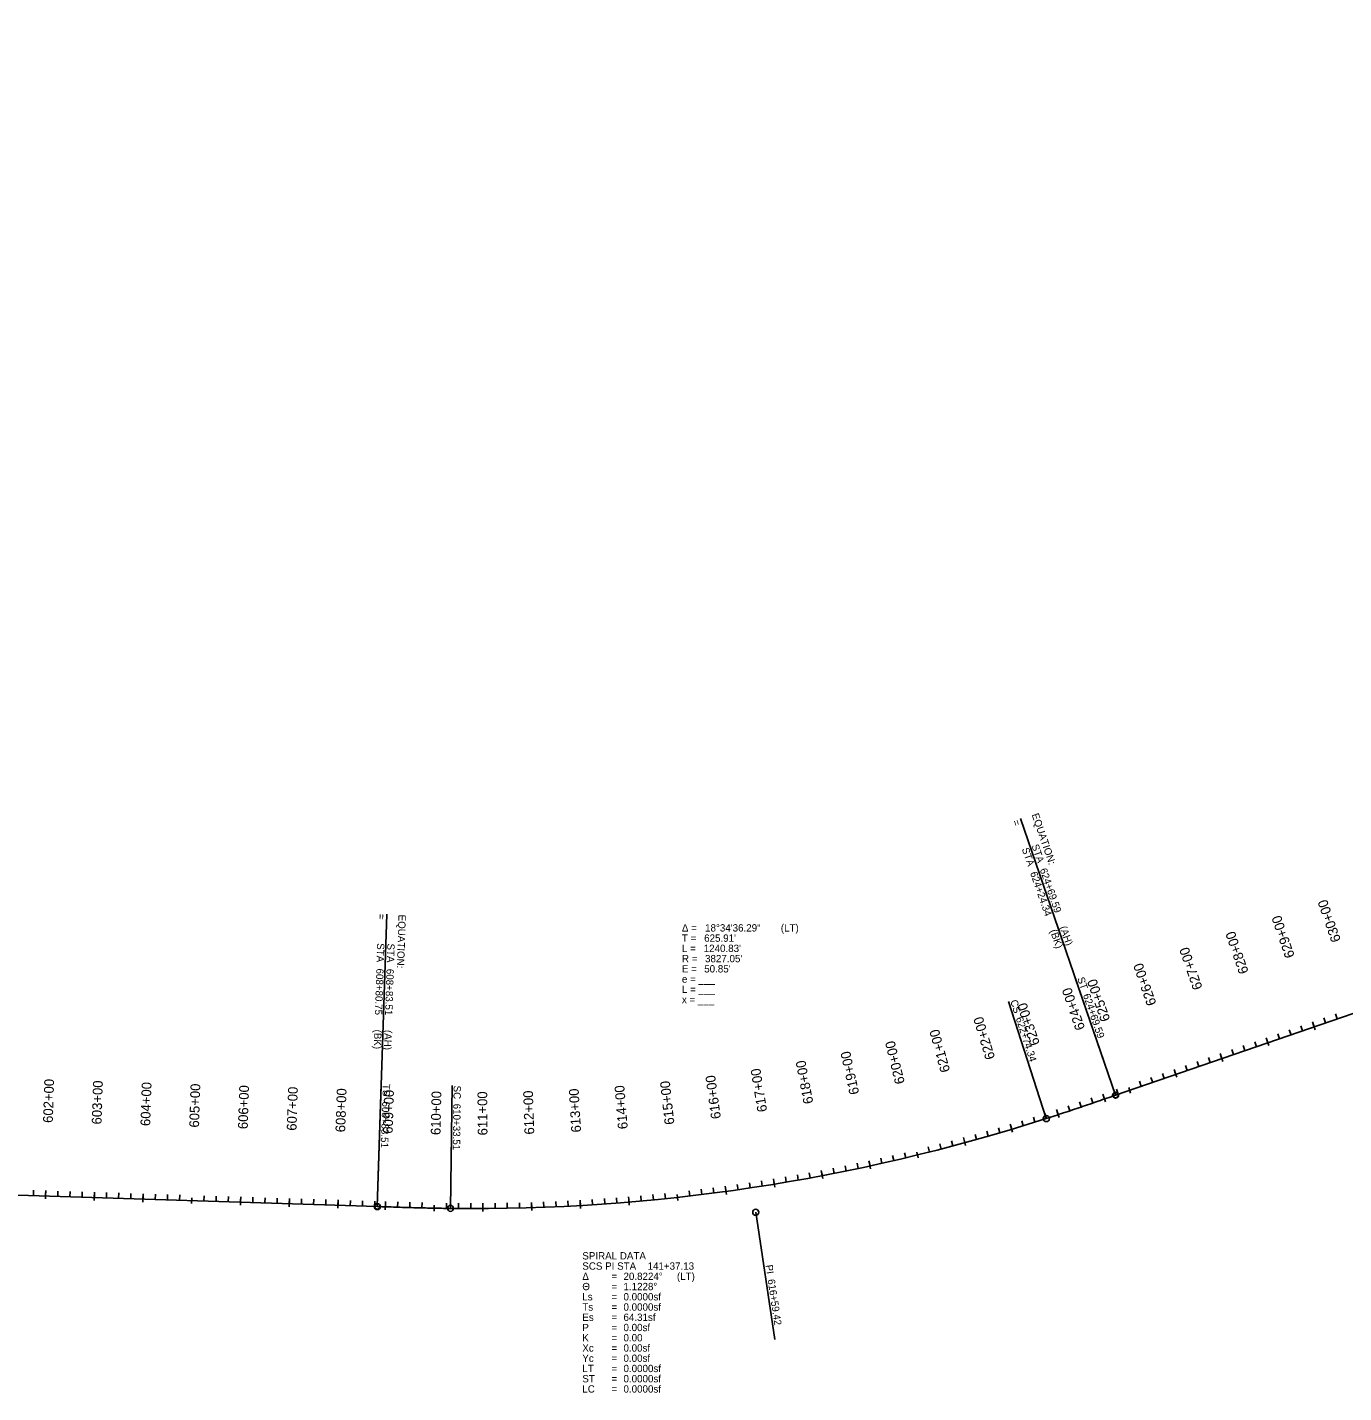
# Model space of a CAD drawing. Extents: x 22693007 to 22771804, y 6223023 to 6251673.
# Drawn here: x 22737783 to 22740482, y 6235125 to 6237925 of the extents above; entities that cross this region are included whole.
import ezdxf

# ---------------------------------------------------------------- set-up
doc = ezdxf.new("R2010")
doc.units = 0
for name, color, linetype in [('Default', 7, 'Continuous'), ('Draft_2', 7, 'Continuous'), ('NamedBoundary', 7, 'Continuous'), ('SheetBorder', 7, 'Continuous'), ('TextAlignment', 7, 'Continuous')]:
    doc.layers.add(name, color=color, linetype=linetype)

msp = doc.modelspace()

# ---------------------------------------------------------------- linework, layer by layer
at = {"layer": 'Default'}
for p, q in [((22740013.9, 6235734.9), (22746376.2, 6237924.7)), ((22734977.1, 6235619), (22738500.2, 6235506.5))]:
    msp.add_line(p, q, dxfattribs=at)
msp.add_arc((22738697.4, 6239329.4), 3827, 269.2933, 287.8701, dxfattribs=at)
for points in [[(22739871.8, 6235687), (22739883.7, 6235690.8), (22739907.4, 6235698.6), (22739943, 6235710.6), (22739978.5, 6235722.7), (22740002.1, 6235730.8), (22740013.9, 6235734.9)], [(22738500.2, 6235506.5), (22738512.7, 6235506.1), (22738537.7, 6235505.3), (22738575.2, 6235504.2), (22738612.7, 6235503.2), (22738637.7, 6235502.8), (22738650.2, 6235502.7)]]:
    msp.add_open_spline(points, degree=3, dxfattribs=at)
at = {"layer": 'Draft_2'}
for p, q in [((22740420.9, 6235875), (22740417.3, 6235885.3)), ((22740326.3, 6235842.4), (22740322.8, 6235852.8)), ((22740231.8, 6235809.9), (22740228.2, 6235820.2)), ((22740137.2, 6235777.3), (22740133.7, 6235787.7)), ((22739990.9, 6235727), (22739987.4, 6235737.3)), ((22740040.7, 6235750.6), (22740044.7, 6235739)), ((22739896.2, 6235695), (22739892.8, 6235705.3)), ((22739800.8, 6235664.9), (22739797.7, 6235675.3)), ((22739704.7, 6235637.3), (22739701.8, 6235647.8)), ((22739606.4, 6235618.2), (22739609.3, 6235606.3)), ((22739510.4, 6235589.7), (22739508.1, 6235600.4)), ((22739314, 6235552.4), (22739312.2, 6235563.1)), ((22739412.5, 6235569.8), (22739410.4, 6235580.5)), ((22737819.8, 6235528.2), (22737820.2, 6235539.1)), ((22737919.8, 6235525), (22737920.1, 6235535.9)), ((22738019.7, 6235521.8), (22738020.1, 6235532.7)), ((22739215.1, 6235537.5), (22739213.6, 6235548.4)), ((22738119.9, 6235524.7), (22738119.5, 6235512.5)), ((22738219.6, 6235515.4), (22738220, 6235526.3)), ((22738319.6, 6235512.2), (22738319.9, 6235523.2)), ((22738419.5, 6235509), (22738419.9, 6235520)), ((22738516.7, 6235505.9), (22738517.1, 6235516.9)), ((22738616.8, 6235509.3), (22738616.6, 6235497.1)), ((22738716.7, 6235502.4), (22738716.6, 6235513.3)), ((22738816.7, 6235504.2), (22738816.3, 6235515.1)), ((22738916.6, 6235508.6), (22738915.9, 6235519.6)), ((22739016.3, 6235515.7), (22739015.4, 6235526.6)), ((22739115.2, 6235531.4), (22739116.5, 6235519.2))]:
    msp.add_line(p, q, dxfattribs=at)
at = {"layer": 'NamedBoundary'}
for p, q in [((22740013.9, 6235734.9), (22746376.2, 6237924.7)), ((22734977.1, 6235619), (22738500.2, 6235506.5))]:
    msp.add_line(p, q, dxfattribs=at)
msp.add_arc((22738697.4, 6239329.4), 3827, 269.2933, 287.8701, dxfattribs=at)
for points in [[(22739871.8, 6235687), (22739883.7, 6235690.8), (22739907.4, 6235698.6), (22739943, 6235710.6), (22739978.5, 6235722.7), (22740002.1, 6235730.8), (22740013.9, 6235734.9)], [(22738500.2, 6235506.5), (22738512.7, 6235506.1), (22738537.7, 6235505.3), (22738575.2, 6235504.2), (22738612.7, 6235503.2), (22738637.7, 6235502.8), (22738650.2, 6235502.7)]]:
    msp.add_open_spline(points, degree=3, dxfattribs=at)
at = {"layer": 'SheetBorder'}
for p, q in [((22740468.2, 6235891.2), (22740464.6, 6235901.6)), ((22740373.6, 6235858.7), (22740370.1, 6235869)), ((22740397.3, 6235866.8), (22740393.7, 6235877.2)), ((22740418.9, 6235880.8), (22740422.9, 6235869.2)), ((22740444.5, 6235883.1), (22740441, 6235893.4)), ((22740302.7, 6235834.3), (22740299.1, 6235844.6)), ((22740324.3, 6235848.2), (22740328.3, 6235836.6)), ((22740350, 6235850.6), (22740346.4, 6235860.9)), ((22740229.8, 6235815.7), (22740233.8, 6235804.1)), ((22740255.4, 6235818), (22740251.9, 6235828.3)), ((22740279.1, 6235826.2), (22740275.5, 6235836.5)), ((22740160.9, 6235785.5), (22740157.3, 6235795.8)), ((22740184.5, 6235793.6), (22740180.9, 6235803.9)), ((22740208.1, 6235801.7), (22740204.6, 6235812.1)), ((22740066.3, 6235752.9), (22740062.8, 6235763.3)), ((22740089.9, 6235761.1), (22740086.4, 6235771.4)), ((22740113.6, 6235769.2), (22740110, 6235779.5)), ((22740135.2, 6235783.1), (22740139.2, 6235771.5)), ((22739967.3, 6235718.9), (22739963.7, 6235729.2)), ((22739988.9, 6235732.8), (22739992.9, 6235721.2)), ((22740019, 6235736.7), (22740015.5, 6235747)), ((22740040.7, 6235750.6), (22740044.7, 6235739)), ((22739894.3, 6235700.8), (22739898.1, 6235689.1)), ((22739919.9, 6235702.8), (22739916.4, 6235713.2)), ((22739943.6, 6235710.8), (22739940.1, 6235721.2)), ((22739824.7, 6235672.2), (22739821.5, 6235682.6)), ((22739848.6, 6235679.6), (22739845.3, 6235690)), ((22739872.4, 6235687.2), (22739869, 6235697.6)), ((22739728.8, 6235644), (22739725.8, 6235654.5)), ((22739752.8, 6235650.8), (22739749.8, 6235661.3)), ((22739776.8, 6235657.8), (22739773.8, 6235668.2)), ((22739799, 6235670.7), (22739802.6, 6235659)), ((22739583.6, 6235606.4), (22739581, 6235617)), ((22739606.4, 6235618.2), (22739609.3, 6235606.3)), ((22739632.1, 6235618.3), (22739629.5, 6235628.9)), ((22739656.4, 6235624.5), (22739653.6, 6235635)), ((22739680.5, 6235630.8), (22739677.7, 6235641.4)), ((22739703.1, 6235643.2), (22739706.3, 6235631.4)), ((22739461.5, 6235579.4), (22739459.3, 6235590.1)), ((22739486, 6235584.5), (22739483.7, 6235595.2)), ((22739509.1, 6235595.7), (22739511.7, 6235583.7)), ((22739534.9, 6235595.1), (22739532.5, 6235605.8)), ((22739559.2, 6235600.7), (22739556.8, 6235611.3)), ((22739338.6, 6235556.5), (22739336.8, 6235567.2)), ((22739363.3, 6235560.7), (22739361.4, 6235571.5)), ((22739387.9, 6235565.2), (22739385.9, 6235575.9)), ((22739411.3, 6235575.8), (22739413.6, 6235563.8)), ((22739437, 6235574.5), (22739434.9, 6235585.2)), ((22737794.9, 6235529), (22737795.2, 6235539.9)), ((22737820, 6235534.3), (22737819.7, 6235522.1)), ((22737844.8, 6235527.4), (22737845.2, 6235538.3)), ((22737869.8, 6235526.6), (22737870.2, 6235537.5)), ((22737894.8, 6235525.8), (22737895.2, 6235536.7)), ((22737944.8, 6235524.2), (22737945.1, 6235535.1)), ((22737969.8, 6235523.4), (22737970.1, 6235534.3)), ((22737994.8, 6235522.6), (22737995.1, 6235533.5)), ((22739091, 6235522.7), (22739089.9, 6235533.5)), ((22739140.7, 6235528.1), (22739139.4, 6235539)), ((22739165.5, 6235531.1), (22739164.2, 6235541.9)), ((22739190.3, 6235534.2), (22739188.9, 6235545.1)), ((22739214.3, 6235543.6), (22739215.9, 6235531.5)), ((22739239.9, 6235541), (22739238.3, 6235551.8)), ((22739264.6, 6235544.6), (22739263, 6235555.4)), ((22739289.3, 6235548.4), (22739287.6, 6235559.2)), ((22739313, 6235558.4), (22739315, 6235546.3)), ((22737920, 6235531.1), (22737919.6, 6235518.9)), ((22738019.9, 6235527.9), (22738019.5, 6235515.7)), ((22738044.7, 6235521), (22738045.1, 6235531.9)), ((22738069.7, 6235520.2), (22738070.1, 6235531.1)), ((22738094.7, 6235519.4), (22738095.1, 6235530.3)), ((22738119.9, 6235524.7), (22738119.5, 6235512.5)), ((22738144.7, 6235517.8), (22738145, 6235528.7)), ((22738169.7, 6235517), (22738170, 6235527.9)), ((22738194.7, 6235516.2), (22738195, 6235527.1)), ((22738219.8, 6235521.5), (22738219.4, 6235509.3)), ((22738244.6, 6235514.6), (22738245, 6235525.5)), ((22738269.6, 6235513.8), (22738270, 6235524.7)), ((22738294.6, 6235513), (22738295, 6235524)), ((22738319.8, 6235518.4), (22738319.4, 6235506.1)), ((22738344.6, 6235511.4), (22738344.9, 6235522.4)), ((22738369.6, 6235510.6), (22738369.9, 6235521.6)), ((22738394.6, 6235509.8), (22738394.9, 6235520.8)), ((22738419.7, 6235515.2), (22738419.3, 6235502.9)), ((22738444.5, 6235508.2), (22738444.9, 6235519.2)), ((22738469.5, 6235507.4), (22738469.9, 6235518.4)), ((22738494.5, 6235506.7), (22738494.9, 6235517.6)), ((22738516.9, 6235512.1), (22738516.5, 6235499.8)), ((22738541.7, 6235505.2), (22738542.1, 6235516.1)), ((22738566.7, 6235504.4), (22738567, 6235515.3)), ((22738591.7, 6235503.8), (22738592, 6235514.7)), ((22738616.8, 6235509.3), (22738616.6, 6235497.1)), ((22738641.7, 6235502.8), (22738641.8, 6235513.7)), ((22738666.7, 6235502.5), (22738666.8, 6235513.4)), ((22738691.7, 6235502.4), (22738691.7, 6235513.3)), ((22738716.7, 6235508.5), (22738716.7, 6235496.3)), ((22738741.7, 6235502.6), (22738741.6, 6235513.5)), ((22738766.7, 6235503), (22738766.5, 6235513.9)), ((22738791.7, 6235503.5), (22738791.4, 6235514.4)), ((22738816.5, 6235510.3), (22738816.9, 6235498.1)), ((22738841.7, 6235505.1), (22738841.2, 6235516)), ((22738866.6, 6235506.1), (22738866.1, 6235517)), ((22738891.6, 6235507.3), (22738891, 6235518.2)), ((22738916.2, 6235514.8), (22738916.9, 6235502.5)), ((22738941.5, 6235510.2), (22738940.8, 6235521.1)), ((22738966.5, 6235511.8), (22738965.7, 6235522.7)), ((22738991.4, 6235513.7), (22738990.6, 6235524.6)), ((22739015.8, 6235521.8), (22739016.8, 6235509.6)), ((22739041.2, 6235517.8), (22739040.2, 6235528.7)), ((22739066.1, 6235520.2), (22739065.1, 6235531)), ((22739115.2, 6235531.4), (22739116.5, 6235519.2))]:
    msp.add_line(p, q, dxfattribs=at)
at = {"layer": 'TextAlignment'}
for p, q in [((22740013.9, 6235734.9), (22739818.6, 6236302.2)), ((22739818.6, 6236302.2), (22739818.6, 6236302.2)), ((22738500.2, 6235506.5), (22738519.4, 6236106.2)), ((22738519.4, 6236106.2), (22738519.4, 6236106.2)), ((22740013.9, 6235734.9), (22739931.9, 6235973.2)), ((22739931.9, 6235973.2), (22739931.9, 6235973.2)), ((22739871.8, 6235687), (22739794.4, 6235926.8)), ((22739794.4, 6235926.8), (22739794.4, 6235926.8)), ((22739871.8, 6235687), (22739794.4, 6235926.8)), ((22739794.4, 6235926.8), (22739794.4, 6235926.8)), ((22738500.2, 6235506.5), (22738508.3, 6235758.3)), ((22738508.3, 6235758.3), (22738508.3, 6235758.3)), ((22738650.2, 6235502.7), (22738653.3, 6235754.6)), ((22738650.2, 6235502.7), (22738653.3, 6235754.6)), ((22738653.3, 6235754.6), (22738653.3, 6235754.6)), ((22738653.3, 6235754.6), (22738653.3, 6235754.6)), ((22739276.1, 6235494.9), (22739315.5, 6235233.9)), ((22739315.5, 6235233.9), (22739315.5, 6235233.9))]:
    msp.add_line(p, q, dxfattribs=at)
for centre, radius in [((22740013.9, 6235734.9), 6.24), ((22740013.9, 6235734.9), 5.34), ((22739871.8, 6235687), 6.24), ((22739871.8, 6235687), 6.24), ((22738500.2, 6235506.5), 6.24), ((22738500.2, 6235506.5), 5.34), ((22738650.2, 6235502.7), 6.24), ((22738650.2, 6235502.7), 6.24), ((22739276.1, 6235494.9), 6.24)]:
    msp.add_circle(centre, radius, dxfattribs=at)

# ---------------------------------------------------------------- texts
at = {"layer": 'Draft_2'}
for s, rotation, p in [('630+00', 108.9929, (22740476.1, 6236052.6)), ('625+00', 108.9929, (22740003.3, 6235889.9)), ('620+00', 103.7629, (22739581.9, 6235760.3)), ('605+00', 88.1705, (22738134.5, 6235668.2)), ('615+00', 96.2773, (22739109.4, 6235675.5)), ('610+00', 88.8477, (22738629.7, 6235653))]:
    msp.add_text(s, height=20.04, rotation=rotation, dxfattribs=at).set_placement(p)
at = {"layer": 'SheetBorder'}
for s, rotation, p in [('630+00', 108.9929, (22740476.1, 6236052.6)), ('629+00', 108.9929, (22740381.5, 6236020.1)), ('628+00', 108.9929, (22740287, 6235987.5)), ('627+00', 108.9929, (22740192.4, 6235955)), ('626+00', 108.9929, (22740097.9, 6235922.4)), ('624+00', 108.9634, (22739951.6, 6235872.1)), ('625+00', 108.9929, (22740003.3, 6235889.9)), ('623+00', 108.2214, (22739858.8, 6235840.6)), ('621+00', 105.26, (22739674.9, 6235784.7)), ('622+00', 106.7572, (22739767.1, 6235811.4)), ('620+00', 103.7629, (22739581.9, 6235760.3)), ('619+00', 102.2658, (22739488.4, 6235738.4)), ('617+00', 99.2715, (22739299.7, 6235702)), ('618+00', 100.7687, (22739394.3, 6235719)), ('602+00', 88.1705, (22737834.7, 6235677.8)), ('603+00', 88.1705, (22737934.6, 6235674.6)), ('604+00', 88.1705, (22738034.5, 6235671.4)), ('605+00', 88.1705, (22738134.5, 6235668.2)), ('615+00', 96.2773, (22739109.4, 6235675.5)), ('616+00', 97.7744, (22739204.7, 6235687.5)), ('606+00', 88.1705, (22738234.4, 6235665)), ('607+00', 88.1705, (22738334.4, 6235661.8)), ('608+00', 88.1705, (22738434.3, 6235658.6)), ('609+00', 88.1841, (22738531.5, 6235655.5)), ('610+00', 88.8477, (22738629.7, 6235653)), ('611+00', 90.2888, (22738726, 6235652.5)), ('612+00', 91.7859, (22738822, 6235654.5)), ('613+00', 93.283, (22738918, 6235659)), ('614+00', 94.7802, (22739013.8, 6235666))]:
    msp.add_text(s, height=20.04, rotation=rotation, dxfattribs=at).set_placement(p)
at = {"layer": 'TextAlignment'}
for s, rotation, p in [('=', 288.9929, (22739801.9, 6236296.5)), ('EQUATION:', 288.9929, (22739841.6, 6236310.1)), ('STA ', 288.9929, (22739821.4, 6236239.7)), ('STA ', 288.9929, (22739841.3, 6236246.6)), ('624+24.34', 288.9929, (22739838.4, 6236190.6)), ('624+69.59', 288.9929, (22739858.2, 6236197.5)), ('=', 268.1705, (22738501.7, 6236106.7)), ('EQUATION:', 268.1705, (22738543.7, 6236105.4)), ('(BK)', 288.9929, (22739879.1, 6236072.1)), ('(AH)', 288.9929, (22739899, 6236079)), ('STA ', 268.1705, (22738499.8, 6236046.8)), ('STA ', 268.1705, (22738520.8, 6236046.1)), ('608+80.75', 268.1705, (22738498.2, 6235994.8)), ('608+83.51', 268.1705, (22738519.1, 6235994.2)), ('ST', 288.9929, (22739935, 6235974.2)), ('CS', 287.8701, (22739797.6, 6235927.9)), ('CS', 287.8701, (22739797.6, 6235927.9)), ('624+69.59', 288.9929, (22739946.7, 6235940.2)), ('622+74.34', 287.8701, (22739809, 6235892.6)), ('622+74.34', 287.8701, (22739809, 6235892.6)), ('(BK)', 268.1705, (22738494.2, 6235869.6)), ('(AH)', 268.1705, (22738515.1, 6235868.9)), ('TS', 268.1705, (22738511.6, 6235758.2)), ('SC', 269.2933, (22738656.6, 6235754.6)), ('SC', 269.2933, (22738656.6, 6235754.6)), ('608+83.51', 268.1705, (22738510.4, 6235722.2)), ('610+33.51', 269.2933, (22738656.1, 6235717.5)), ('610+33.51', 269.2933, (22738656.1, 6235717.5)), ('PI ', 278.5817, (22739295.8, 6235386.1)), ('616+59.42', 278.5817, (22739300.3, 6235356.5))]:
    msp.add_text(s, height=15, rotation=rotation, dxfattribs=at).set_placement(p)
for s, p in [('Δ = ', (22739124.7, 6236070.5)), ("625.91'", (22739170.3, 6236049.5)), ('18°34\'36.29"', (22739172.2, 6236070.5)), (' (LT)', (22739321.9, 6236070.5)), ('T = ', (22739124.7, 6236049.5)), ('L = ', (22739124.7, 6236028.5)), ("1240.83'", (22739169.4, 6236028.5)), ('R = ', (22739124.7, 6236007.5)), ("3827.05'", (22739172.1, 6236007.5)), ('E = ', (22739124.7, 6235986.5)), ("50.85'", (22739170.4, 6235986.5)), ('e = ___ ', (22739124.7, 6235965.5)), ('L = ___', (22739124.7, 6235944.5)), ('x = ___', (22739124.7, 6235923.5)), ('SPIRAL DATA', (22738920.5, 6235398)), ('Δ', (22738920.5, 6235356)), ('SCS PI STA ', (22738920.5, 6235377)), ('= ', (22738980.5, 6235356)), ('20.8224°', (22739004.9, 6235356)), ('141+37.13', (22739054.3, 6235377)), (' (LT)', (22739108.9, 6235356)), ('Θ ', (22738920.5, 6235335)), ('= ', (22738980.5, 6235335)), ('1.1228°', (22739004.9, 6235335)), ('Ls', (22738920.5, 6235314)), ('= ', (22738980.5, 6235314)), ('0.0000sf', (22739004.9, 6235314)), ('0.0000sf', (22739004.9, 6235293)), ('Ts', (22738920.5, 6235293)), ('Es', (22738920.5, 6235272)), ('= ', (22738980.5, 6235293)), ('= ', (22738980.5, 6235272)), ('64.31sf', (22739004.9, 6235272)), ('P', (22738920.5, 6235251)), ('= ', (22738980.5, 6235251)), ('0.00sf', (22739004.9, 6235251)), ('K', (22738920.5, 6235230)), ('= ', (22738980.5, 6235230)), ('0.00', (22739004.9, 6235230)), ('0.00sf', (22739004.9, 6235209)), ('Yc', (22738920.5, 6235188)), ('Xc', (22738920.5, 6235209)), ('= ', (22738980.5, 6235209)), ('= ', (22738980.5, 6235188)), ('0.00sf', (22739004.9, 6235188)), ('LT', (22738920.5, 6235167)), ('= ', (22738980.5, 6235167)), ('0.0000sf', (22739004.9, 6235167)), ('ST ', (22738920.5, 6235146)), ('= ', (22738980.5, 6235146)), ('0.0000sf', (22739004.9, 6235146)), ('0.0000sf', (22739004.9, 6235125)), ('LC', (22738920.5, 6235125)), ('= ', (22738980.5, 6235125))]:
    msp.add_text(s, height=15, dxfattribs=at).set_placement(p)

doc.saveas('drawing.dxf')
